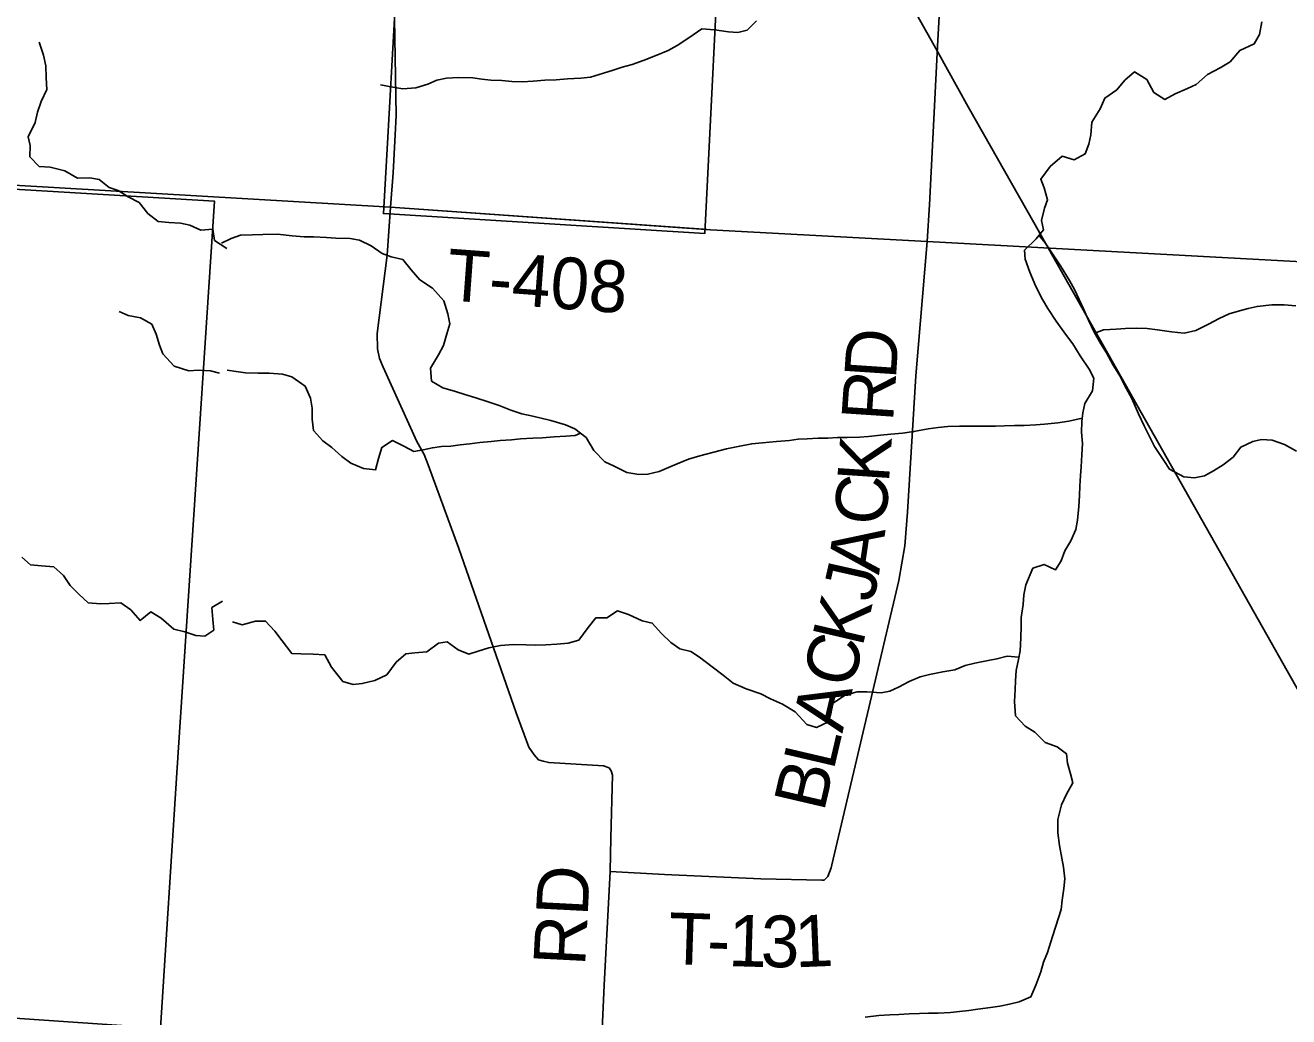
# Model space of a CAD drawing. Extents: x 1759416 to 2214760, y 252598 to 1116833.
# Drawn here: x 1967340 to 1974666, y 846970 to 852721 of the extents above; entities that cross this region are included whole.
import ezdxf

# ---------------------------------------------------------------- set-up
doc = ezdxf.new("R2010")
doc.units = 0
for name, color, linetype in [('GM_X_Corporation', 7, 'Continuous'), ('GM_X_Minor_River', 7, 'Continuous'), ('GM_X_Rail_Line', 7, 'Continuous'), ('GM_X_Section', 7, 'Continuous'), ('GM_X_Township', 7, 'Continuous'), ('GM_X_Township_Road', 7, 'Continuous'), ('GM_X_Township_Road_Text', 7, 'Continuous')]:
    doc.layers.add(name, color=color, linetype=linetype)

msp = doc.modelspace()

# ---------------------------------------------------------------- linework, layer by layer
at = {"layer": 'GM_X_Corporation'}
msp.add_lwpolyline([(1975643.6, 857013.7), (1976064, 856092.6), (1976447.7, 855255.3), (1973972.1, 855298.5), (1973846.6, 853367.6), (1972675, 853439.5), (1971379.5, 853490.5), (1971279.9, 851512.2), (1970876, 851538), (1969416.7, 851629), (1969440, 852037.2), (1969481.1, 852759.7), (1969519, 853381.4), (1970078.4, 853401), (1970078.4, 853842), (1969545.9, 853823.4), (1969604.9, 854773.9), (1971448.9, 854741.7), (1971525.5, 856205), (1969887.5, 856205), (1969900.9, 856970.1)], dxfattribs=at)
at = {"layer": 'GM_X_Minor_River'}
for points in [[(1971579.9, 852746), (1971525.6, 852692.2), (1971471.5, 852678.5), (1971417.6, 852682.8), (1971335.6, 852695.3), (1971263.7, 852699.8), (1971187.4, 852648.1), (1971119.2, 852604.4), (1971067.1, 852574.6), (1970992.9, 852542.9), (1970928.8, 852519.2), (1970858.7, 852493.6), (1970800.6, 852477.9), (1970748.5, 852460.1), (1970692.4, 852442.4), (1970618.4, 852420.8), (1970562.3, 852415.1), (1970484.3, 852409.5), (1970418.3, 852403.9), (1970352.3, 852402.3), (1970284.3, 852396.7), (1970222.3, 852393), (1970162.3, 852395.4), (1970104.4, 852399.7), (1970040.4, 852402.1), (1969988.4, 852408.4), (1969934.5, 852416.8), (1969854.5, 852417.3), (1969782.5, 852413.7), (1969726.5, 852402), (1969674.4, 852380.2), (1969604.2, 852358.6), (1969530.2, 852353), (1969472.3, 852361.3), (1969400.4, 852375.8)], [(1974509.2, 852740.8), (1974496.8, 852666.7), (1974466.5, 852612.7), (1974382.3, 852575.1), (1974326, 852509.2), (1974267.8, 852473.5), (1974195.6, 852435.8), (1974129.4, 852378), (1974079.2, 852354.3), (1974007.1, 852322.6), (1973946.9, 852290.9), (1973883.2, 852331.3), (1973843.6, 852405.8), (1973771.8, 852450.3), (1973715.6, 852402.5), (1973669.3, 852346.7), (1973599, 852298.9), (1973572.7, 852236.9), (1973524.3, 852159), (1973517.9, 852084.8), (1973507.6, 852030.7), (1973485.4, 851974.7), (1973421.2, 851941), (1973353.3, 851961.4), (1973283, 851901.7), (1973228.6, 851827.8), (1973248.4, 851777.5), (1973268, 851709.2), (1973249.7, 851659.2), (1973233.4, 851589.1), (1973245.1, 851534.9), (1973200.8, 851483), (1973134.5, 851417.2), (1973138.2, 851365), (1973165.8, 851288.7), (1973199.4, 851206.2), (1973239, 851129.8), (1973268.7, 851077.4), (1973318.3, 851005), (1973371.9, 850928.4), (1973413.6, 850874), (1973457.2, 850803.6), (1973508.8, 850727), (1973536.5, 850674.8), (1973528.1, 850600.6), (1973483.7, 850526.6), (1973471.4, 850472.5), (1973467.2, 850422.4), (1973464.8, 850360.3), (1973470.5, 850294.1), (1973466.2, 850229.9), (1973461.8, 850159.7), (1973459.5, 850109.6), (1973455.2, 850047.5), (1973452.9, 849993.3), (1973448.6, 849929.2), (1973442.1, 849851), (1973431.9, 849796.9), (1973403.5, 849730.9), (1973367.2, 849672.9), (1973346.9, 849614.9), (1973314.7, 849562.9), (1973248.8, 849593.4), (1973182.7, 849571.7), (1973142.2, 849475.7), (1973129.9, 849417.6), (1973125.6, 849361.5), (1973115.2, 849285.3), (1973115, 849235.2), (1973112.6, 849167), (1973108.2, 849092.8), (1973100, 849042.7), (1973085.6, 848978.6), (1973081.3, 848918.5), (1973079, 848868.3), (1973076.7, 848798.2), (1973082.2, 848715.9), (1973137.9, 848655.4), (1973193.7, 848621), (1973253.4, 848560.4), (1973323.2, 848536), (1973377, 848495.5), (1973382.7, 848441.3), (1973400.4, 848379.1), (1973414.1, 848326.8), (1973377.8, 848260.9), (1973349.4, 848198.8), (1973327, 848114.8), (1973326.6, 848036.5), (1973336.2, 847962.3), (1973349.8, 847890), (1973359.5, 847837.8), (1973367.2, 847769.5), (1973362.9, 847713.4), (1973352.5, 847645.3), (1973346.2, 847591.2)], [(1967420.3, 852622), (1967445.3, 852547.5), (1967460.4, 852485.1), (1967461.5, 852416.9), (1967464.6, 852348.7), (1967431.6, 852279), (1967410.8, 852217.1), (1967398, 852157.1), (1967356.8, 852073.4), (1967368.1, 852023.1), (1967367.2, 851956.9), (1967420.5, 851902.1), (1967484.5, 851897.2), (1967570.3, 851876), (1967643.8, 851834.9), (1967713.9, 851836), (1967767.8, 851827.2), (1967827.2, 851780.3), (1967879, 851763.5), (1967936.6, 851726.7), (1968000.2, 851693.7), (1968051.4, 851628.9), (1968110.8, 851581.9), (1968172.8, 851577.1), (1968240.8, 851572.2), (1968294.7, 851561.4), (1968358.3, 851532.5), (1968428.4, 851537.5), (1968437.6, 851473.2), (1968509, 851426.2)], [(1973468.9, 850442.5), (1973391.2, 850424.9), (1973327.2, 850415.2), (1973249.1, 850407.7), (1973199.1, 850404), (1973131.1, 850400.3), (1973075.1, 850398.7), (1973017.1, 850397), (1972965.1, 850395.3), (1972757.2, 850396.5), (1972689.2, 850392.9), (1972633.2, 850387.2), (1972575.1, 850379.6), (1972493.1, 850364), (1972427, 850354.4), (1972359, 850348.8), (1972299, 850343.1), (1972229, 850335.5), (1972177, 850331.8), (1972105, 850330.2), (1972049, 850330.5), (1971993, 850326.8), (1971937, 850325.2), (1971873, 850321.5), (1971821, 850319.8), (1971771, 850312.1), (1971696.9, 850306.5), (1971614.9, 850299), (1971552.9, 850293.3), (1971482.9, 850279.7), (1971406.8, 850264.1), (1971332.7, 850244.5), (1971250.6, 850222.9), (1971186.5, 850203.2), (1971120.4, 850177.5), (1971070.3, 850155.8), (1971016.2, 850132), (1970950.1, 850116.4), (1970898.1, 850114.7), (1970828.2, 850127.1), (1970754.4, 850163.7), (1970700.5, 850188), (1970636.9, 850254.6), (1970593.3, 850329.1), (1970527.6, 850379.6), (1970471.7, 850404), (1970387.9, 850428.6), (1970284, 850453.2), (1970220.1, 850467.7), (1970156.2, 850488.1), (1970088.4, 850514.6), (1970024.5, 850537), (1969952.7, 850559.5), (1969888.8, 850579.9), (1969834.9, 850596.3), (1969761, 850618.8), (1969695.2, 850657.3), (1969689.6, 850731.5), (1969736, 850809.4), (1969764.3, 850863.4), (1969784.7, 850931.5), (1969801, 850989.6), (1969791.3, 851047.8), (1969767.7, 851122.1), (1969702.1, 851196.7), (1969628.4, 851245.3), (1969578.7, 851301.8), (1969529, 851362.2), (1969461.1, 851378.7), (1969409.2, 851397), (1969345.5, 851441.5), (1969277.7, 851474), (1969223.7, 851484.3), (1969141.8, 851486.8), (1969087.8, 851489.2), (1969011.8, 851493.6), (1968957.8, 851493.9), (1968887.9, 851500.4), (1968801.9, 851508.9), (1968718, 851507.4), (1968658, 851505.7), (1968588, 851504.1), (1968533.9, 851484.4), (1968477.7, 851456.7)], [(1973218, 851503.2), (1973254.7, 851458.6), (1973342, 851325.7), (1973395.5, 851241.2), (1973423.2, 851188.8), (1973450.9, 851130.5), (1973476.6, 851076.2), (1973504.3, 851009.9), (1973537.9, 850941.5), (1973577.5, 850873.1), (1973609.2, 850820.7), (1973648.9, 850750.3), (1973690.5, 850681.9), (1973716.2, 850629.6), (1973755.8, 850555.1), (1973795.3, 850466.6), (1973826.9, 850398.3), (1973856.6, 850339.9), (1973888.3, 850277.6), (1973941.9, 850197), (1973975.6, 850146.7), (1974057.3, 850102.1), (1974119.3, 850095.7), (1974177.3, 850107.4), (1974229.5, 850137.2), (1974285.7, 850170.9), (1974343.9, 850216.7), (1974388.2, 850274.6), (1974458.3, 850306.3), (1974508.4, 850318), (1974570.3, 850313.6), (1974642.2, 850289.2), (1974712, 850250.6)], [(1967885.6, 851061.5), (1967937.3, 851036.8), (1968009.2, 851023.8), (1968074.7, 850986.8), (1968100, 850928.3), (1968119.1, 850865.9), (1968138.5, 850815.5), (1968203.6, 850744.4), (1968289.3, 850717.2), (1968345.4, 850720.4), (1968413.4, 850717.5), (1968467.2, 850702.8)], [(1973541.7, 850934.9), (1973591.9, 850955.2), (1973666, 850958.8), (1973720, 850962.5), (1973782, 850964.1), (1973845.9, 850961.7), (1973905.9, 850953.4), (1973985.8, 850942.8), (1974059.7, 850934.4), (1974127.8, 850950), (1974200, 850987.7), (1974262.1, 851019.4), (1974320.3, 851047.2), (1974380.4, 851064.9), (1974430.4, 851078.6), (1974482.5, 851090.3), (1974568.5, 851099.9), (1974640.5, 851099.4), (1974706.4, 851093)], [(1970559.8, 850354.9), (1970529.4, 850341.5), (1970475.4, 850337.8), (1970407.4, 850334.2), (1970337.4, 850328.6), (1970283.4, 850326.9), (1970211.4, 850321.3), (1970159.3, 850315.6), (1970093.3, 850312), (1970041.3, 850306.2), (1969975.3, 850300.6), (1969917.3, 850292.9), (1969861.3, 850287.2), (1969807.2, 850279.5), (1969753.2, 850277.9), (1969701.2, 850270.2), (1969647.2, 850258.4), (1969593.1, 850248.7), (1969539.3, 850277.1), (1969469.5, 850311.6), (1969407.3, 850271.9), (1969388.9, 850207.8), (1969370.6, 850141.7), (1969300.7, 850150.2), (1969228.8, 850180.7), (1969175, 850219.1), (1969117.3, 850271.6), (1969065.6, 850310), (1969011.9, 850370.5), (1969004.2, 850436.7), (1969004.6, 850500.9), (1968994.9, 850557.1), (1968963.3, 850627.5), (1968885.6, 850682.1), (1968831.6, 850696.4), (1968753.7, 850702.9), (1968689.7, 850703.3), (1968617.7, 850705.7), (1968563.8, 850712.1), (1968511.8, 850720.4)], [(1967319.9, 849635.2), (1967371.3, 849590.4), (1967435.3, 849585.6), (1967505.3, 849580.6), (1967562.7, 849529.7), (1967599.9, 849471), (1967651.2, 849420.2), (1967704.6, 849371.3), (1967776.6, 849364.4), (1967826.7, 849367.7), (1967894.8, 849370.8), (1967952.3, 849329.9), (1968005.5, 849269), (1968068.2, 849318.3), (1968127.8, 849281.4), (1968201, 849218.3), (1968264.8, 849203.4), (1968328.6, 849180.4), (1968380.6, 849177.7), (1968433.1, 849213.1), (1968427.9, 849273.4), (1968422.8, 849343.6), (1968483.4, 849380.9)], [(1973102.1, 849055.8), (1973034.1, 849061.2), (1972974, 849045.5), (1972924, 849035.7), (1972845.9, 849020.1), (1972789.8, 849006.4), (1972729.7, 848982.7), (1972659.7, 848971.1), (1972583.6, 848955.5), (1972529.6, 848941.8), (1972465.4, 848914.1), (1972403.3, 848882.3), (1972353.2, 848858.6), (1972303.1, 848848.8), (1972221.2, 848855.3), (1972163.2, 848853.7), (1972095.1, 848836), (1972020.8, 848786.3), (1972012.6, 848736.2), (1971998.3, 848680.2), (1971928.1, 848648.5), (1971872.2, 848664.9), (1971804.6, 848739.5), (1971730.9, 848784), (1971661.1, 848814.5), (1971605.2, 848842.9), (1971519.4, 848871.5), (1971445.6, 848904), (1971385.9, 848950.5), (1971322.1, 848999), (1971250.4, 849055.6), (1971198.6, 849088), (1971134.7, 849104.4), (1971082.9, 849140.8), (1971029.2, 849193.3), (1970975.6, 849253.8), (1970917.6, 849266.2), (1970837.8, 849302.8), (1970774, 849325.2), (1970711.8, 849283.4), (1970647.8, 849283.8), (1970603.5, 849227.9), (1970549.1, 849154), (1970489, 849136.3), (1970423, 849130.7), (1970359, 849127.1), (1970301, 849125.4), (1970245, 849127.7), (1970171.1, 849128.2), (1970095.1, 849122.6), (1970029, 849108.9), (1969966.9, 849091.3), (1969912.8, 849073.5), (1969851, 849098), (1969787.2, 849144.5), (1969737.2, 849136.7), (1969669, 849087), (1969599, 849081.4), (1969546.9, 849075.7), (1969490.7, 849025.9), (1969436.3, 848954), (1969366.2, 848920.3), (1969294.1, 848902.7), (1969242.1, 848897), (1969182.2, 848915.4), (1969116.6, 848998), (1969077, 849068.4), (1969009, 849072.8), (1968937.1, 849075.3), (1968885.1, 849077.6), (1968829.5, 849150.1), (1968787.8, 849206.5), (1968734.1, 849265), (1968676.1, 849265.3), (1968598, 849243.7), (1968542.1, 849260.1)], [(1973346.2, 847591.2), (1973315.7, 847495), (1973295.4, 847435), (1973267, 847342.9), (1973244.7, 847286.9), (1973228.4, 847230.8), (1973200, 847152.8), (1973171.6, 847084.7), (1973103.5, 847057), (1973047.4, 847043.3), (1972991.4, 847031.6), (1972937.3, 847023.9), (1972863.3, 847014.3), (1972811.3, 847006.6), (1972757.3, 847000.9), (1972705.2, 846995.2), (1972633.2, 846991.6), (1972577.2, 846989.9), (1972525.3, 846988.2), (1972465.3, 846986.6), (1972405.2, 846982.9), (1972353.3, 846981.2), (1972289.3, 846977.6), (1972209.2, 846968)]]:
    msp.add_lwpolyline(points, dxfattribs=at)
at = {"layer": 'GM_X_Rail_Line'}
msp.add_lwpolyline([(1975008.5, 848353.2), (1973366.5, 851261.6), (1973188.4, 851577.3), (1972807.9, 852248.1), (1972627.7, 852573.5), (1972190.5, 853349.5)], dxfattribs=at)
at = {"layer": 'GM_X_Section'}
msp.add_lwpolyline([(1965690.7, 851865), (1968437.4, 851701.1), (1968218.4, 848384.8), (1968124.1, 846904), (1965363.5, 847093.9)], close=True, dxfattribs=at)
at = {"layer": 'GM_X_Township'}
for points in [[(1976896.4, 857732.8), (1976716.8, 854704.7), (1976712.4, 854611.6), (1976682.7, 854121.4), (1976641.9, 853591.6), (1976523.6, 851253), (1972570.3, 851466.9), (1971312.5, 851534.9), (1969457.3, 851665.2), (1966709.5, 851825.5), (1962913.8, 852046.9), (1958781.9, 852319.2), (1955561, 852512.8)], [(1955561, 852512.8), (1958781.9, 852319.2), (1962913.8, 852046.9), (1966709.5, 851825.5), (1969457.3, 851665.2), (1971312.5, 851534.9), (1972570.3, 851466.9), (1976523.6, 851253)]]:
    msp.add_lwpolyline(points, dxfattribs=at)
at = {"layer": 'GM_X_Township_Road'}
for points in [[(1972570.3, 851466.9), (1972584, 851679.8), (1972630.1, 852597.5), (1972675, 853439.5), (1972675.9, 853456.1)], [(1969485.4, 852085.2), (1969491.6, 852197.2), (1969481.1, 852759.7), (1969523.3, 853451.9)], [(1969457.3, 851665.2), (1969473.1, 851864.2), (1969485.4, 852085.2)], [(1970623.1, 845532.3), (1970696.6, 847152.3), (1970731.2, 847811.9), (1970735.3, 848008.3), (1970745.7, 848371.2), (1970737.7, 848397.3), (1970725.7, 848413.4), (1970693.7, 848425.4), (1970375.6, 848443.9), (1970343.6, 848452), (1970315.6, 848460), (1970291.6, 848488.2), (1970259.6, 848534.3), (1970185.8, 848732.9), (1969854.5, 849685.7), (1969676.9, 850171.1), (1969652.9, 850231.3), (1969611, 850307.6), (1969415.3, 850736.9), (1969393.3, 850789), (1969383.4, 850843.2), (1969381.4, 850933.4), (1969438.1, 851388.3), (1969457.3, 851665.2)], [(1969457.3, 851665.2), (1971272.5, 851537.8)], [(1971272.5, 851537.8), (1971312.5, 851534.9), (1972570.3, 851466.9)], [(1972017.5, 847850.7), (1972262.6, 848892.4), (1972405.2, 849499.7), (1972439.4, 849702.1), (1972455.6, 849896.6), (1972504.3, 850688.4), (1972570.3, 851466.9)], [(1970731.2, 847811.9), (1971047.2, 847795.4), (1971605.4, 847770.5), (1971959.5, 847762), (1971971.5, 847762), (1971993.6, 847784), (1972013.6, 847834.1), (1972017.5, 847850.7)]]:
    msp.add_lwpolyline(points, dxfattribs=at)

# ---------------------------------------------------------------- texts
at = {"layer": 'GM_X_Township_Road_Text'}
for s, rotation, p in [('T-408', 355.79479, (1969776.6, 851126.4)), ('D', 86.16045, (1972387.9, 850663.7)), ('R', 86.15658, (1972371.4, 850417.8)), ('K', 86.16226, (1972347.6, 850062.2)), ('C', 86.07083, (1972330.6, 849815.9)), ('A', 81.72057, (1972290, 849529.9)), ('J', 77.28972, (1972254.4, 849367.7)), ('K', 76.86078, (1972193.8, 849108.2)), ('C', 76.83231, (1972137.7, 848868.1)), ('A', 76.82987, (1972077.5, 848611)), ('L', 76.83064, (1972026.4, 848392.5)), ('B', 76.83278, (1971970.2, 848152.6)), ('RD', 87.03883, (1970585.8, 847260.6)), ('T', 358.10969, (1971065.6, 847275.6)), ('1', 358.27646, (1971413.9, 847264.2)), ('3', 359.18896, (1971603.9, 847258.5)), ('1', 2.40023, (1971807, 847256.1)), ('-', 358.11677, (1971289.9, 847268.2))]:
    msp.add_text(s, height=300, rotation=rotation, dxfattribs=at).set_placement(p)

doc.saveas('drawing.dxf')
